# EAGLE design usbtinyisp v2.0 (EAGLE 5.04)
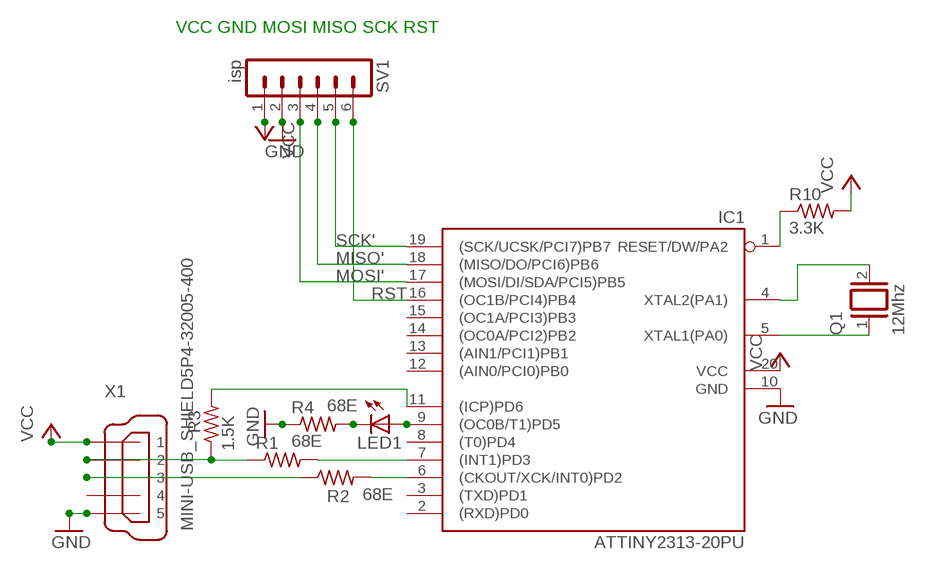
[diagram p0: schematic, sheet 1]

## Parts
IC1  ATTINY2313-20PU  ATTINY2313-20P  [DIL20]
LED1  LED3MM  [LED3MM]
Q1  12Mhz  XTAL/S  [QS]
R1  68E  R-US_0207/10  [0207/10]
R2  68E  R-US_0207/10  [0207/10]
R3  1.5K  R-US_0207/10  [0207/10]
R4  68E  R-US_0207/10  [0207/10]
R10  3.3K  R-US_0207/10  [0207/10]
SV1  isp  MA06-1  [MA06-1]
X1  MINI-USB_SHIELD5P4-32005-400  [32005-400]

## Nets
GND: IC1.10(GND) R4.1 SV1.2 X1.5
MISO': IC1.18((MISO/DO/PCI6)PB6) SV1.4
MOSI': IC1.17((MOSI/DI/SDA/PCI5)PB5) SV1.3
N$1: R1.1 R3.1 X1.2
N$2: R2.1 X1.3
N$3: IC1.7((INT1)PD3) R1.2
N$4: IC1.5(XTAL1(PA0)) Q1.1
N$5: IC1.4(XTAL2(PA1)) Q1.2
N$6: IC1.6((CKOUT/XCK/INT0)PD2) R2.2
N$8: IC1.9((OC0B/T1)PD5) LED1.A
N$9: IC1.1(RESET/DW/PA2) R10.1
N$10: LED1.K(C) R4.2
N$16: IC1.11((ICP)PD6) R3.2
RST: IC1.16((OC1B/PCI4)PB4) SV1.6
SCK': IC1.19((SCK/UCSK/PCI7)PB7) SV1.5
VCC: IC1.20(VCC) R10.2 SV1.1 X1.1
Unconnected: IC1.2((RXD)PD0) IC1.3((TXD)PD1) IC1.8((T0)PD4) IC1.12((AIN0/PCI0)PB0) IC1.13((AIN1/PCI1)PB1) IC1.14((OC0A/PCI2)PB2) IC1.15((OC1A/PCI3)PB3) X1.4 X1.M1(S1) X1.M2(S2) X1.M3(S3) X1.M4(S4)

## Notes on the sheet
- VCC GND MOSI MISO SCK RST

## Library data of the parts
IC1 = avr:ATTINY2313: MICROCONTROLLER 2 Kbytes FLASH 128 bytes SRAM 128 bytes EEPROM USART USI
LED1 = led:LED: LED
Q1 = special:XTAL/S: CRYSTAL
R1 R4 R10 = rcl-ez:R-US_: RESISTOR, American symbol
R2 R3 = rcl:R-US_: RESISTOR, American symbol
SV1 = con-lstb:MA06-1: PIN HEADER
X1 = con-cypressindustries:MINI-USB_SHIELD5P4-: MINI USB-B R/A W/O POST 5 pol. Source: www.cypressindustries.com

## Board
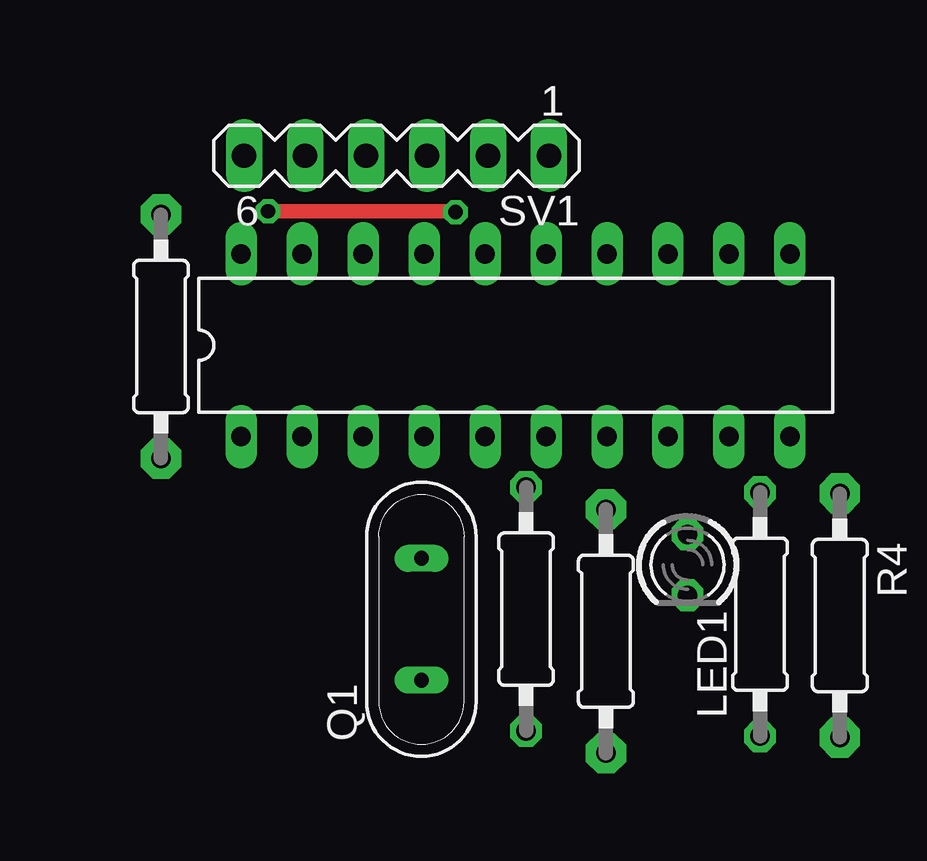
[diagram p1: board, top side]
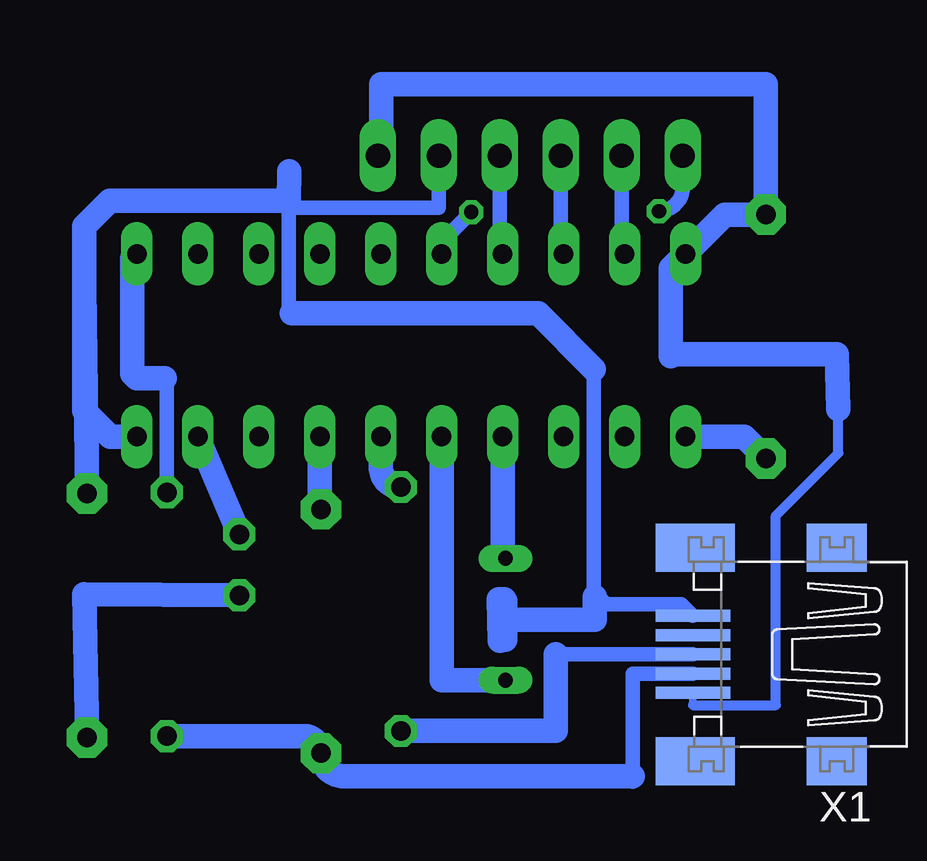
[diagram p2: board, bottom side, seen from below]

No outline drawn. Coordinates in mm, seen from the top.
Copper layers (1*16): Top 0.035mm / dielectric 1.5mm / Bottom 0.035mm
Design rules "default": minimum track width 12mil, minimum drill 24mil, track to track 12mil, track to pad 12mil, pad to pad 12mil, via to via 12mil, smd to smd 0mil, copper to edge 20mil, drill to drill 8mil, minimum pad ring 10mil, minimum via ring 8mil, stop-mask expansion 4mil, vias tented up to drill 0mil, thermal gap 10mil

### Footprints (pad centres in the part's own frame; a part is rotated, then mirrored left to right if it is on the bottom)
DIL20 = drill 0.813 long: 1 -11.43,-3.81; 2 -8.89,-3.81; 3 -6.35,-3.81; 4 -3.81,-3.81; 5 -1.27,-3.81; 6 1.27,-3.81; 7 3.81,-3.81; 8 6.35,-3.81; 9 8.89,-3.81; 10 11.43,-3.81; 11 11.43,3.81; 12 8.89,3.81; 13 6.35,3.81; 14 3.81,3.81; 15 1.27,3.81; 16 -1.27,3.81; 17 -3.81,3.81; 18 -6.35,3.81; 19 -8.89,3.81; 20 -11.43,3.81
LED3MM = drill 0.813 octagon: A -1.27,0; K 1.27,0
QS = drill 0.61 long: 1 -2.54,0; 2 2.54,0
0207/10 = drill 0.813 pad 1.676 octagon: 1 -5.08,0; 2 5.08,0
0207/10' = drill 0.813 octagon: 1 -5.08,0; 2 5.08,0
MA06-1 = drill 1.016 long: 1 -6.35,0; 2 -3.81,0; 3 -1.27,0; 4 1.27,0; 5 3.81,0; 6 6.35,0
32005-400 = smd 3.1 x 0.5: 1 3,1.6; 2 3,0.8; 3 3,0; 4 3,-0.8; 5 3,-1.6 | smd 2.5 x 2: M1 -3,-4.45; M2 -3,4.45 | smd 3.3 x 2: M3 2.9,4.45; M4 2.9,-4.45

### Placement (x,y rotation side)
IC1  22.19,43.96 0 top
LED1  29.36,34.82 270 top
Q1  18.27,32.55 90 top
R1  25.96,32.05 90 top
R2  68E  [0207/10']  22.63,32.97 90 top
R3  1.5K  [0207/10']  32.38,32.76 90 top
R4  35.7,32.7 270 top
R10  7.42,44.33 90 top
SV1  17.23,51.86 180 top
X1  7.46,31.09 180 bottom

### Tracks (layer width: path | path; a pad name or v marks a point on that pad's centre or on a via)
GND
  Bottom 0.61: X1.5 10.94,33.16 14.06,33.16 14.59,33.69 14.59,42.97 | 27.18,45.29 27.3,45.42 27.3,49.69 | 27.3,49.69 27.3,49.98 | SV1.2 21.04,49.69 27.3,49.69
  Bottom 1.016: 27.27,51.21 27.3,49.98 34.76,49.98 35.81,48.93 35.81,46.37 | 35.81,46.37 35.81,41.23 34.73,40.16 IC1.10 | 35.81,46.37 R4.1 | 14.59,42.97 16.91,45.29 27.18,45.29
MISO'
  Bottom 0.61: SV1.4 15.96,47.77 IC1.18
MOSI'
  Bottom 0.61: SV1.3 18.5,47.77 IC1.17
N$1
  Bottom 0.61: X1.2 12.96,30.29 12.96,26.01 12.96,25.78
  Bottom 1.016: R3.1 26.66,27.68 arc90 R1.1 arc-90 25,26.01 12.96,26.01
N$2
  Bottom 0.61: X1.3 16.16,31.09 16.33,31.09
  Bottom 1.016: R2.1 16.16,27.89 16.16,31.09
N$3
  Bottom 1.016: R1.2 arc90 26,37.17 IC1.7
N$4
  Bottom 1.016: IC1.5 20.92,30.01 Q1.1
N$5
  Bottom 0.61: Q1.2 18.38,35.09
  Bottom 1.016: 18.38,35.09 IC1.4
N$6
  Bottom 1.016: R2.2 arc90 23.46,38.88 IC1.6
N$7
  Bottom 1.016: 14.54,33.48 14.54,32.53 18.33,32.53 18.33,33.33 18.27,33.33 18.27,31.69 18.5,31.66 18.54,33.38 18.33,33.38 18.33,33.16 18.38,33.16
N$8
  Bottom 1.016: IC1.9 LED1.A
N$9
  Bottom 1.016: R10.1 8.32,40.16 IC1.1
N$10
  Bottom 1.016: LED1.K 35.81,33.59 R4.2
N$16
  Bottom 0.61: 32.46,42.6 32.38,42.52 R3.2
  Bottom 1.016: IC1.11 33.81,47.58 33.81,42.78 33.63,42.6 32.46,42.6
RST  (via drill 0.6)
  Top 0.61: v11.88,49.55 19.65,49.55 arc-90 v19.69,49.51
  Bottom 0.61: SV1.6 10.88,50.54 arc90 v11.88,49.55 | v19.69,49.51 20.92,48.28 IC1.16
SCK'
  Bottom 0.61: SV1.5 13.42,47.77 IC1.19
VCC
  Bottom 0.305: X1.1 10.46,28.97
  Bottom 0.406: 10.46,28.97 7,28.97 7,36.87 4.4,39.46 4.4,41.31
  Bottom 1.016: 4.4,41.31 4.47,43.58 11.29,43.58 11.37,43.5 11.37,47.16 IC1.20 9.13,49.41 R10.2 7.42,54.83 23.43,54.83 23.43,51.86 SV1.1

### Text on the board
tPlace: R1
tNames: CC BY-SA-NC | CircuitsDIY.com | October,2011 | Arup Basak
